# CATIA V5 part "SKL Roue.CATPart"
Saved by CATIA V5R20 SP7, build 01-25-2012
Part number: SKL Roue
Publications: "Plan.1", "Droite.1", "Point.2", "Droite.2", "Excentricité"
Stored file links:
  D:\thinkmotion-MPB\Dropbox\IAO_2011\MMS_GR3\IAO_2011_1501_ybellafdil\SKL Roue.CATPart
  D:\thinkmotion-MPB\Dropbox\IAO_2011\MMS_GR3\IAO_2011_1501_ybellafdil\Assemblage Final.CATProduct
  D:\thinkmotion-MPB\Dropbox\IAO_2011\MMS_GR3\IAO_2011_1501_ybellafdil\SKL Bati.CATPart

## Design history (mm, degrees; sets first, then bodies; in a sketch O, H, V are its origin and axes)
Parameters
  `Excentricité` = 60 mm
Set1
  Point1: linked copy from another document
Body1 (main body)
  Plane1: type Offset, RefPlane yz-plane, Offset 0
  Line1: type Normal, RefPoint Point1, RefSkin Plane1, Start 0, End 20
  Point2: type OnPlane, Support Plane1, H 0, V 60 {= `Excentricité`}, Direction (0, 1, 0)
  Line2: type Normal, RefPoint Point2, RefSkin Plane1, Start 0, End 20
